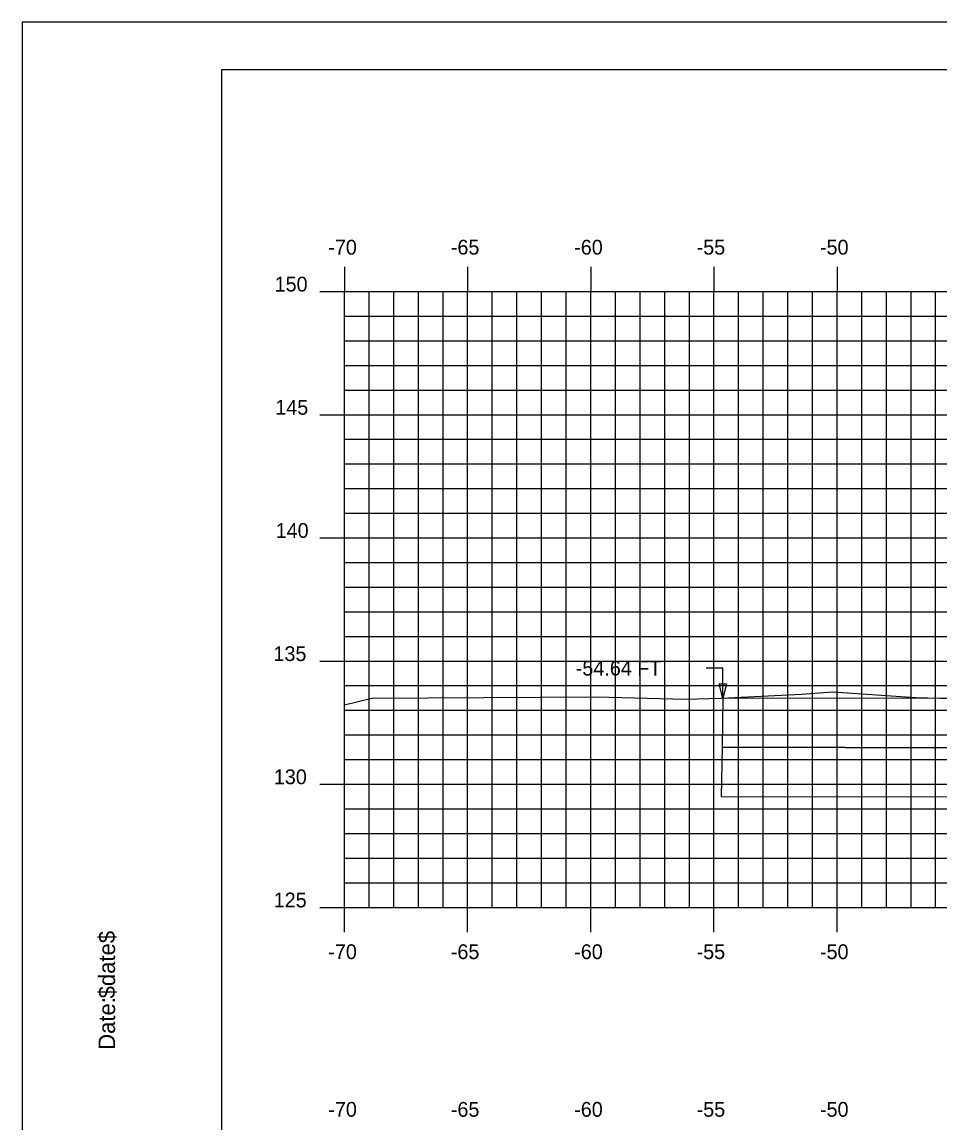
# Model space of a CAD drawing. Extents: x 1143863 to 1144033, y 608981 to 609091.
# Drawn here: x 1143863.5 to 1143900.77, y 609046.58 to 609091.28 of the extents above; entities that cross this region are included whole.
import ezdxf

# ---------------------------------------------------------------- set-up
doc = ezdxf.new("R2010")
doc.units = 0
for name, color, linetype in [('BORDER', 7, 'Continuous'), ('D_Text_Standard', 7, 'Continuous'), ('H_V ANNOTATION', 7, 'Continuous'), ('MAJOR', 7, 'Continuous'), ('MINOR', 7, 'Continuous'), ('PATTERNING', 7, 'Continuous'), ('PLOT BOUNDARY', 7, 'Continuous'), ('S_Roadway_Centerline', 7, 'Continuous')]:
    doc.layers.add(name, color=color, linetype=linetype)

msp = doc.modelspace()

# ---------------------------------------------------------------- linework, layer by layer
at = {"layer": 'BORDER'}
msp.add_lwpolyline([(1143871.593, 608984.335), (1144031.593, 608984.335), (1144031.593, 609089.335), (1143871.593, 609089.335)], close=True, dxfattribs=at)
at = {"layer": 'D_Text_Standard'}
msp.add_lwpolyline([(1143891.952, 609063.832), (1143891.957, 609065.047), (1143891.277, 609065.047)], dxfattribs=at)
msp.add_lwpolyline([(1143891.952, 609063.832), (1143891.809, 609064.414), (1143892.1, 609064.413)], close=True, dxfattribs=at)
at = {"layer": 'MAJOR'}
for p, q in [((1143876.593, 609081.337), (1143876.593, 609080.335)), ((1143881.593, 609081.337), (1143881.593, 609080.335)), ((1143886.593, 609081.337), (1143886.593, 609080.335)), ((1143891.593, 609081.337), (1143891.593, 609080.335)), ((1143896.593, 609081.337), (1143896.593, 609080.335)), ((1143875.591, 609080.335), (1143876.593, 609080.335)), ((1143876.593, 609080.335), (1144016.593, 609080.335)), ((1143876.593, 609055.335), (1143876.593, 609080.335)), ((1143876.593, 609055.335), (1143876.593, 609080.335)), ((1143876.593, 609080.335), (1144016.593, 609080.335)), ((1143881.593, 609055.335), (1143881.593, 609080.335)), ((1143886.593, 609055.335), (1143886.593, 609080.335)), ((1143891.593, 609055.335), (1143891.593, 609080.335)), ((1143896.593, 609055.335), (1143896.593, 609080.335)), ((1143875.591, 609075.335), (1143876.593, 609075.335)), ((1143876.593, 609075.335), (1144016.593, 609075.335)), ((1143875.591, 609070.335), (1143876.593, 609070.335)), ((1143876.593, 609070.335), (1144016.593, 609070.335)), ((1143875.591, 609065.335), (1143876.593, 609065.335)), ((1143876.593, 609065.335), (1144016.593, 609065.335)), ((1143875.591, 609060.335), (1143876.593, 609060.335)), ((1143876.593, 609060.335), (1144016.593, 609060.335)), ((1143875.591, 609055.335), (1143876.593, 609055.335)), ((1143876.593, 609055.335), (1144016.593, 609055.335)), ((1143876.593, 609055.335), (1144016.593, 609055.335)), ((1143876.593, 609054.333), (1143876.593, 609055.335)), ((1143881.593, 609054.333), (1143881.593, 609055.335)), ((1143886.593, 609054.333), (1143886.593, 609055.335)), ((1143891.593, 609054.333), (1143891.593, 609055.335)), ((1143896.593, 609054.333), (1143896.593, 609055.335))]:
    msp.add_line(p, q, dxfattribs=at)
at = {"layer": 'MINOR'}
for p, q in [((1143877.593, 609055.335), (1143877.593, 609080.335)), ((1143878.593, 609055.335), (1143878.593, 609080.335)), ((1143879.593, 609055.335), (1143879.593, 609080.335)), ((1143880.593, 609055.335), (1143880.593, 609080.335)), ((1143882.593, 609055.335), (1143882.593, 609080.335)), ((1143883.593, 609055.335), (1143883.593, 609080.335)), ((1143884.593, 609055.335), (1143884.593, 609080.335)), ((1143885.593, 609055.335), (1143885.593, 609080.335)), ((1143887.593, 609055.335), (1143887.593, 609080.335)), ((1143888.593, 609055.335), (1143888.593, 609080.335)), ((1143889.593, 609055.335), (1143889.593, 609080.335)), ((1143890.593, 609055.335), (1143890.593, 609080.335)), ((1143892.593, 609055.335), (1143892.593, 609080.335)), ((1143893.593, 609055.335), (1143893.593, 609080.335)), ((1143894.593, 609055.335), (1143894.593, 609080.335)), ((1143895.593, 609055.335), (1143895.593, 609080.335)), ((1143897.593, 609055.335), (1143897.593, 609080.335)), ((1143898.593, 609055.335), (1143898.593, 609080.335)), ((1143899.593, 609055.335), (1143899.593, 609080.335)), ((1143900.593, 609055.335), (1143900.593, 609080.335)), ((1143876.593, 609079.335), (1144016.593, 609079.335)), ((1143876.593, 609079.335), (1143877.595, 609079.335)), ((1143876.593, 609078.335), (1144016.593, 609078.335)), ((1143876.593, 609078.335), (1143877.595, 609078.335)), ((1143876.593, 609077.335), (1144016.593, 609077.335)), ((1143876.593, 609077.335), (1143877.595, 609077.335)), ((1143876.593, 609076.335), (1144016.593, 609076.335)), ((1143876.593, 609076.335), (1143877.595, 609076.335)), ((1143876.593, 609074.335), (1144016.593, 609074.335)), ((1143876.593, 609074.335), (1143877.595, 609074.335)), ((1143876.593, 609073.335), (1144016.593, 609073.335)), ((1143876.593, 609073.335), (1143877.595, 609073.335)), ((1143876.593, 609072.335), (1144016.593, 609072.335)), ((1143876.593, 609072.335), (1143877.595, 609072.335)), ((1143876.593, 609071.335), (1144016.593, 609071.335)), ((1143876.593, 609071.335), (1143877.595, 609071.335)), ((1143876.593, 609069.335), (1144016.593, 609069.335)), ((1143876.593, 609069.335), (1143877.595, 609069.335)), ((1143876.593, 609068.335), (1144016.593, 609068.335)), ((1143876.593, 609068.335), (1143877.595, 609068.335)), ((1143876.593, 609067.335), (1144016.593, 609067.335)), ((1143876.593, 609067.335), (1143877.595, 609067.335)), ((1143876.593, 609066.335), (1144016.593, 609066.335)), ((1143876.593, 609066.335), (1143877.595, 609066.335)), ((1143876.593, 609064.335), (1144016.593, 609064.335)), ((1143876.593, 609064.335), (1143877.595, 609064.335)), ((1143876.593, 609063.335), (1144016.593, 609063.335)), ((1143876.593, 609063.335), (1143877.595, 609063.335)), ((1143876.593, 609062.335), (1144016.593, 609062.335)), ((1143876.593, 609062.335), (1143877.595, 609062.335)), ((1143876.593, 609061.335), (1144016.593, 609061.335)), ((1143876.593, 609061.335), (1143877.595, 609061.335)), ((1143876.593, 609059.335), (1144016.593, 609059.335)), ((1143876.593, 609059.335), (1143877.595, 609059.335)), ((1143876.593, 609058.335), (1144016.593, 609058.335)), ((1143876.593, 609058.335), (1143877.595, 609058.335)), ((1143876.593, 609057.335), (1144016.593, 609057.335)), ((1143876.593, 609057.335), (1143877.595, 609057.335)), ((1143876.593, 609056.335), (1144016.593, 609056.335)), ((1143876.593, 609056.335), (1143877.595, 609056.335))]:
    msp.add_line(p, q, dxfattribs=at)
at = {"layer": 'PATTERNING'}
for points in [[(1143901.953, 609063.817), (1143891.952, 609063.832), (1143891.92, 609061.832), (1143901.924, 609061.817)], [(1143901.921, 609061.817), (1143891.92, 609061.832), (1143891.888, 609059.832), (1143901.892, 609059.818)]]:
    msp.add_lwpolyline(points, close=True, dxfattribs=at)
at = {"layer": 'PLOT BOUNDARY'}
msp.add_lwpolyline([(1143863.5, 608981.276), (1144033.5, 608981.276), (1144033.5, 609091.276), (1143863.5, 609091.276)], close=True, dxfattribs=at)
at = {"layer": 'S_Roadway_Centerline'}
msp.add_lwpolyline([(1143876.593, 609063.553), (1143877.704, 609063.826), (1143886.813, 609063.886), (1143890.44, 609063.783), (1143891.884, 609063.828), (1143895.145, 609063.994), (1143896.421, 609064.084), (1143899.776, 609063.855), (1143901.798, 609063.795)], dxfattribs=at)

# ---------------------------------------------------------------- texts
at = {"layer": 'BORDER'}
for s, p in [('$date$', (1143867.278, 609051.64)), ('Date:', (1143867.278, 609049.552))]:
    msp.add_text(s, height=0.6696, rotation=90, dxfattribs=at).set_placement(p)
at = {"layer": 'D_Text_Standard'}
msp.add_text('-54.64 FT', height=0.6, dxfattribs=at).set_placement((1143885.982, 609064.747))
at = {"layer": 'H_V ANNOTATION'}
for s, p in [('-70', (1143875.934, 609081.835)), ('-65', (1143880.91, 609081.835)), ('-60', (1143885.918, 609081.835)), ('-55', (1143890.889, 609081.835)), ('-50', (1143895.897, 609081.835)), ('150', (1143873.755, 609080.335)), ('145', (1143873.782, 609075.335)), ('140', (1143873.798, 609070.335)), ('135', (1143873.707, 609065.335)), ('130', (1143873.723, 609060.335)), ('125', (1143873.717, 609055.335)), ('-70', (1143875.934, 609053.235)), ('-65', (1143880.91, 609053.235)), ('-60', (1143885.918, 609053.235)), ('-55', (1143890.889, 609053.235)), ('-50', (1143895.897, 609053.235)), ('-70', (1143875.934, 609046.835)), ('-65', (1143880.91, 609046.835)), ('-60', (1143885.918, 609046.835)), ('-55', (1143890.889, 609046.835)), ('-50', (1143895.897, 609046.835))]:
    msp.add_text(s, height=0.6, dxfattribs=at).set_placement(p)
at = {"layer": 'MAJOR'}
msp.add_text('-', height=0.006, dxfattribs=at).set_placement((1143876.588, 609055.335))

doc.saveas('drawing.dxf')
